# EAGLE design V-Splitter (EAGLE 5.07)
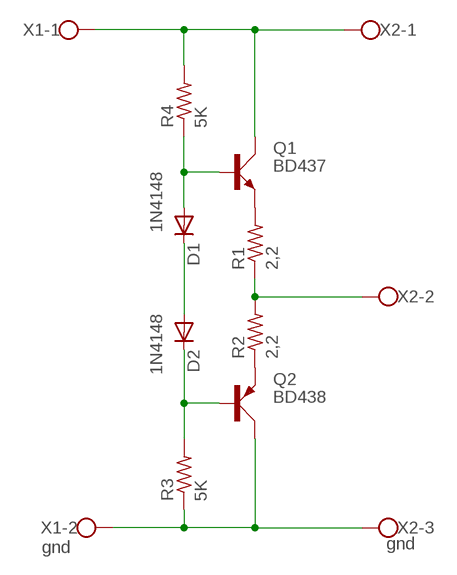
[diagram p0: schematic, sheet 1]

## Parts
D1  1N4148  1N4148DO35-10  [DO35-10]
D2  1N4148  1N4148DO35-10  [DO35-10]
Q1  BD437  [TO126AV]
Q2  BD438  [TO126AV]
R1  2,2  R-US_0207/12  [0207/12]
R2  2,2  R-US_0207/12  [0207/12]
R3  5K  R-US_0207/10  [0207/10]
R4  5K  R-US_0207/10  [0207/10]
X1  gnd  W237-102  [W237-102]
X2  gnd  W237-103  [W237-103]

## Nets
N$1: Q1.E R1.2
N$2: Q2.E R2.1
N$3: R1.1 R2.2 X2.2
N$4: D1.A Q1.B R4.1
N$5: D1.C D2.A
N$6: D2.C Q2.B R3.2
N$7: Q1.C R4.2 X1.1 X2.1
N$8: Q2.C R3.1 X1.2 X2.3

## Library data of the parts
D1 D2 = diode:1N4148: DIODE
Q1 = transistor-power:BD437: NPN TRANSISTOR
Q2 = transistor-power:BD438: PNP TRANSISTOR
R1-R4 = resistor:R-US_: RESISTOR, American symbol
X1 = con-wago-500:W237-102: WAGO SCREW CLAMP
X2 = con-wago-500:W237-103: WAGO SCREW CLAMP

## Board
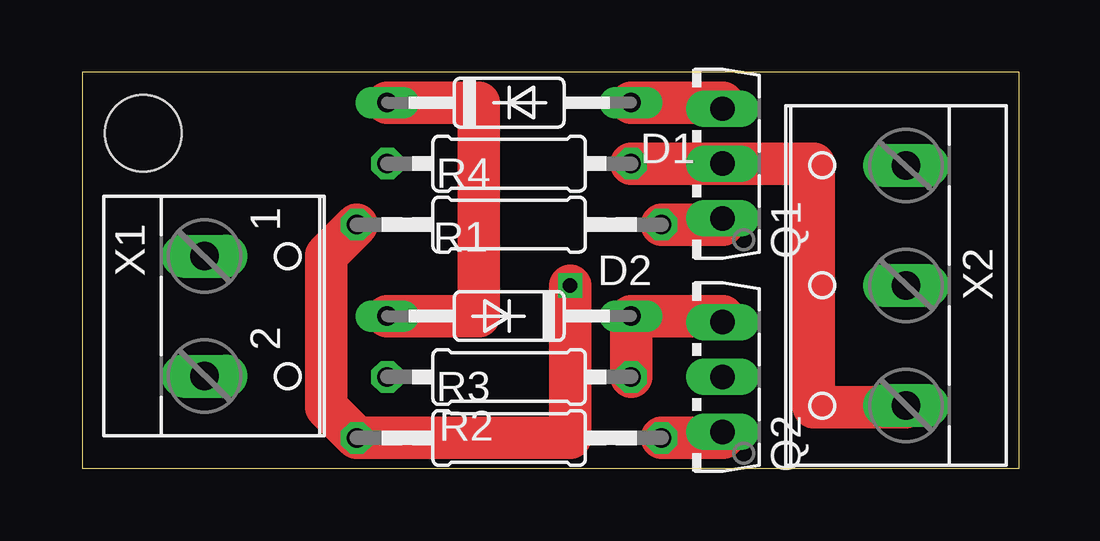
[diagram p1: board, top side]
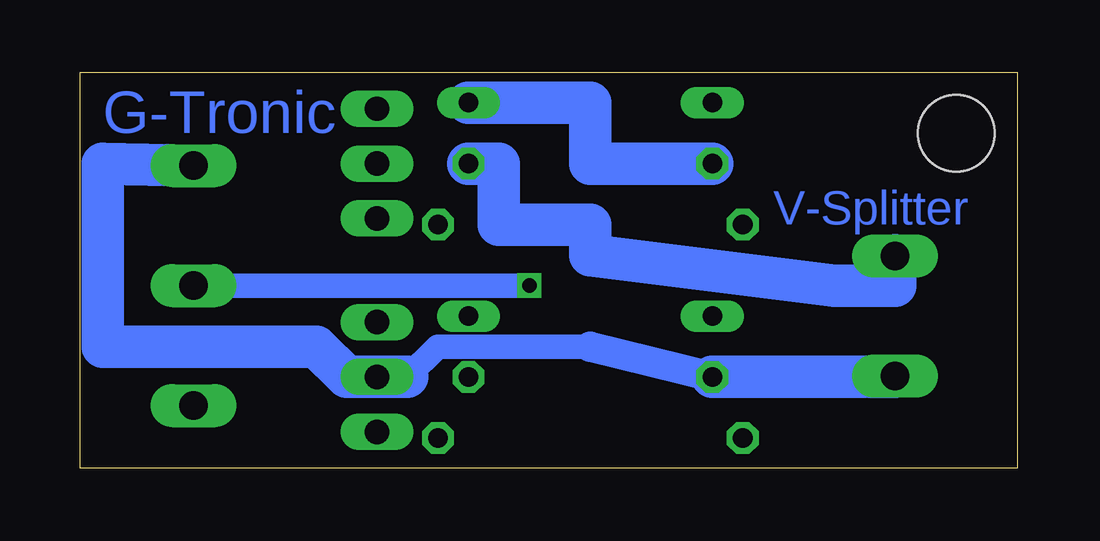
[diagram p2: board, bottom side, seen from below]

Size 39.04 x 16.5 mm. Coordinates in mm from the lower left corner, seen from the top.
Outline: 0,0 39.04,0 39.04,16.5 0,16.5 0,0
Copper layers (1*16): Top 0.035mm / dielectric 1.5mm / Bottom 0.035mm
Design rules "default": minimum track width 10mil, minimum drill 24mil, track to track 8mil, track to pad 8mil, pad to pad 8mil, via to via 8mil, smd to smd 8mil, copper to edge 40mil, drill to drill 8mil, minimum pad ring 10mil, minimum via ring 8mil, stop-mask expansion 4mil, vias tented up to drill 0mil, thermal gap 10mil
Holes 3.2 mm at 2.54,13.97

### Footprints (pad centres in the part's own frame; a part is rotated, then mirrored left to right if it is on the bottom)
DO35-10 = drill 0.813 long: A 5.08,0; C -5.08,0
TO126AV = drill 1.016 long: B 2.286,-1.27; C 0,-1.27; E -2.286,-1.27
0207/12 = drill 0.813 octagon: 1 -6.35,0; 2 6.35,0
0207/10 = drill 0.813 octagon: 1 -5.08,0; 2 5.08,0
W237-102 = drill 1.194 long: 1 -2.5,-1.27; 2 2.5,-1.27
W237-103 = drill 1.194 long: 1 -5,-1.29; 2 0,-1.29; 3 5,-1.29

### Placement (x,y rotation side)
D1  17.78,15.24 0 top
D2  17.78,6.35 180 top
Q1  25.4,12.7 90 top
Q2  25.4,3.81 90 top
R1  17.78,10.16 0 top
R2  17.78,1.27 180 top
R3  17.78,3.81 0 top
R4  17.78,12.7 0 top
X1  6.35,6.35 270 top
X2  33.02,7.62 90 top

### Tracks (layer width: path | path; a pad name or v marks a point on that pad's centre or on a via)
N$1
  Top 0.254: 26.67,10.16 Q1.E
  Top 1.778: R1.2 26.67,10.16
N$2
  Top 0.254: 26.67,1.27 Q2.E
  Top 1.778: R2.1 26.67,1.27
N$3  (via drill 0.6)
  Top 1.778: R1.1 10.16,8.89 10.16,7.62 10.16,5.08 10.16,2.54 R2.2 20.32,1.27 v20.32,7.62
  Bottom 1.016: v20.32,7.62 X2.2
N$4
  Top 0.254: 26.67,15.24 Q1.B
  Top 1.778: D1.A 26.67,15.24
  Bottom 1.778: R4.1 17.78,12.7 17.78,15.24 D1.A
N$5
  Top 1.778: D2.A 16.51,6.35 16.51,15.24 D1.C
N$6
  Top 0.254: 26.67,6.35 Q2.B
  Top 1.778: R3.2 D2.C 26.67,6.35
N$7
  Top 0.254: 34.29,2.54 X2.1
  Top 1.778: Q1.C R4.2 30.48,12.7 30.48,2.54 34.29,2.54
  Bottom 0.254: X1.1 5.08,8.89
  Bottom 1.778: 5.08,8.89 5.08,7.62 7.62,7.62 17.78,8.89 17.78,10.16 21.59,10.16 21.59,12.7 R4.2
N$8
  Bottom 0.254: X1.2 5.08,3.81
  Bottom 1.016: 25.4,3.81 24.13,5.08 17.78,5.08
  Bottom 1.27: R3.1 17.78,5.08
  Bottom 1.778: 5.08,3.81 R3.1 | 25.4,3.81 Q2.C 27.94,3.81 29.21,5.08 38.1,5.08 38.1,12.7 X2.3

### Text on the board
Bottom: G-Tronic | V-Splitter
